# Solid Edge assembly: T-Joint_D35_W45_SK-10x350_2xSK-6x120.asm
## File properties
Author: fknapp
Template: iso metric assembly.asm
Last saved by: fknapp
Revision: 12
Application: Solid Edge
Username: fknapp
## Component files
T-Joint_D35_W45.par
SK Schraube 6x120_ohne_Gewinde.par
SK Schraube 10x350_ohne_Gewinde_22042020.par
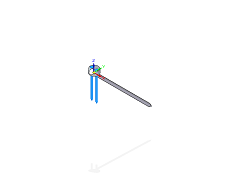
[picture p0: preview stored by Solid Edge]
